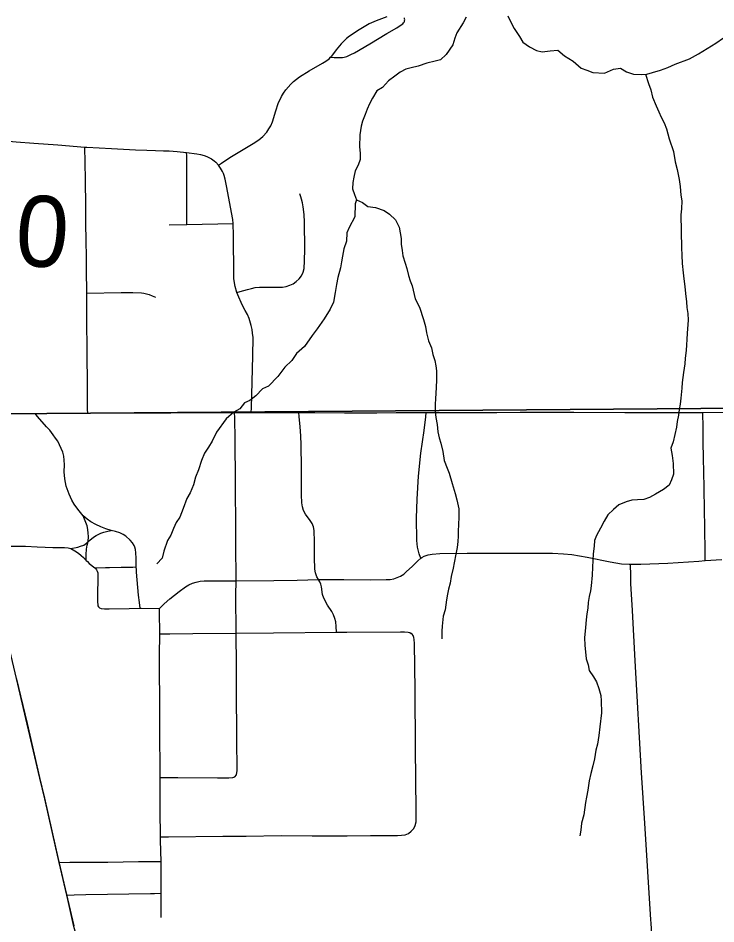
# Model space of a CAD drawing. Extents: x 0 to 34, y 0 to 22.
# Drawn here: x 20.417 to 20.975, y 12.198 to 12.923 of the extents above; entities that cross this region are included whole.
import ezdxf

# ---------------------------------------------------------------- set-up
doc = ezdxf.new("R2010")
doc.units = 0
for name, color, linetype in [('GM_X_City_Street', 7, 'Continuous'), ('GM_X_Corporation', 7, 'Continuous'), ('GM_X_County_Road', 7, 'Continuous'), ('GM_X_Minor_River', 7, 'Continuous'), ('GM_X_Section', 7, 'Continuous'), ('GM_X_State_Route', 7, 'Continuous'), ('GM_X_Township_Road', 7, 'Continuous'), ('GM_X_Township_Road_Text', 7, 'Continuous')]:
    doc.layers.add(name, color=color, linetype=linetype)

msp = doc.modelspace()

# ---------------------------------------------------------------- linework, layer by layer
at = {"layer": 'GM_X_City_Street'}
for points in [[(20.57722, 12.80519), (20.57964, 12.8068), (20.58622, 12.81118), (20.59689, 12.8177), (20.60476, 12.82263), (20.60941, 12.82555), (20.61263, 12.82812), (20.61579, 12.83164), (20.61755, 12.83424), (20.61909, 12.83677), (20.62027, 12.83992), (20.62291, 12.84873), (20.62496, 12.85459), (20.62749, 12.86024), (20.6291, 12.86289), (20.63091, 12.86542), (20.63496, 12.87013), (20.63718, 12.87223), (20.642, 12.87585), (20.6498, 12.88072), (20.66048, 12.88671), (20.66319, 12.88848), (20.66561, 12.89024), (20.6669, 12.89168), (20.66979, 12.89144), (20.67199, 12.89135), (20.67631, 12.8914), (20.67786, 12.89163), (20.67976, 12.89221), (20.68299, 12.89368), (20.686, 12.89514), (20.69832, 12.90233), (20.7119, 12.91069), (20.71982, 12.91516), (20.72261, 12.91692), (20.72481, 12.91846), (20.72533, 12.91905), (20.72574, 12.91959), (20.72602, 12.92025), (20.72616, 12.92088), (20.7262, 12.92161), (20.72616, 12.92237), (20.72599, 12.92317)], [(20.71193, 12.92391), (20.70349, 12.92074), (20.69787, 12.91821), (20.68987, 12.91355), (20.68208, 12.90849), (20.67965, 12.90659), (20.67522, 12.90231), (20.67127, 12.89757), (20.66767, 12.89256), (20.6669, 12.89168)], [(20.55173, 12.75767), (20.5518, 12.7697), (20.55176, 12.78036), (20.55173, 12.78904), (20.55169, 12.79911), (20.55163, 12.81255), (20.55162, 12.81521)], [(20.60323, 12.60701), (20.60347, 12.61094), (20.60466, 12.65257), (20.60476, 12.66728), (20.60447, 12.67073), (20.60398, 12.67369), (20.60329, 12.67675), (20.60161, 12.68237), (20.60023, 12.68553), (20.59856, 12.68879), (20.59599, 12.69343), (20.59254, 12.70132), (20.59193, 12.7033), (20.59047, 12.70803), (20.58988, 12.71089), (20.58939, 12.71434), (20.58929, 12.72668), (20.58918, 12.73921), (20.58909, 12.74888), (20.5888, 12.75841), (20.58855, 12.76161), (20.5834, 12.78871), (20.58238, 12.794), (20.58161, 12.79694), (20.58116, 12.79839), (20.58043, 12.79999), (20.57885, 12.80266), (20.57722, 12.80519)], [(20.59193, 12.7033), (20.59455, 12.70403), (20.60046, 12.70568), (20.60347, 12.70645), (20.60657, 12.70713), (20.60987, 12.70752), (20.61307, 12.70752), (20.62518, 12.70751), (20.62838, 12.70751), (20.63128, 12.70799), (20.63429, 12.70896), (20.63691, 12.71022), (20.63941, 12.71201), (20.64162, 12.71418), (20.64347, 12.71666), (20.64486, 12.71943), (20.64561, 12.72241), (20.64602, 12.72854), (20.64612, 12.73784), (20.64605, 12.75956), (20.64572, 12.76574), (20.64498, 12.77188), (20.64437, 12.77491), (20.64357, 12.7779), (20.64293, 12.77991), (20.64216, 12.78233)], [(20.53753, 12.75727), (20.55173, 12.75767), (20.5888, 12.75841)], [(20.47162, 12.70269), (20.49911, 12.7032), (20.50861, 12.70325), (20.51536, 12.70297), (20.51735, 12.70269), (20.51956, 12.70225), (20.52171, 12.70153), (20.52409, 12.70064), (20.5268, 12.69954)], [(20.47239, 12.60665), (20.47235, 12.60951), (20.47228, 12.61514), (20.47214, 12.62118), (20.47213, 12.63037), (20.4721, 12.6382), (20.47208, 12.64545), (20.47199, 12.65461), (20.47192, 12.66406), (20.47176, 12.6735), (20.47175, 12.68912), (20.47162, 12.70269)], [(20.46868, 12.52426), (20.46651, 12.52691), (20.46445, 12.52967), (20.46168, 12.53378), (20.45971, 12.53691), (20.45743, 12.54175), (20.45517, 12.54819), (20.45408, 12.554), (20.45362, 12.55971), (20.45372, 12.56525), (20.45354, 12.56906), (20.45319, 12.5722), (20.45234, 12.57528), (20.45122, 12.57833), (20.44991, 12.58122), (20.44836, 12.58402), (20.44668, 12.58663), (20.44474, 12.5893), (20.44193, 12.59293), (20.43948, 12.59556), (20.43222, 12.60401), (20.4302, 12.60636)], [(20.53052, 12.31476), (20.53494, 12.31476), (20.54465, 12.31476), (20.57638, 12.31442), (20.58528, 12.31448), (20.58861, 12.31475), (20.5902, 12.31541), (20.59151, 12.31692), (20.59213, 12.32045), (20.59178, 12.34539), (20.59142, 12.38594), (20.5916, 12.40463), (20.59132, 12.43043), (20.59098, 12.46078), (20.59114, 12.47231), (20.59121, 12.47635), (20.59098, 12.49817), (20.59088, 12.51834), (20.59075, 12.54477), (20.59068, 12.55173), (20.59034, 12.58508), (20.59009, 12.6027), (20.59004, 12.60702)], [(20.67156, 12.43116), (20.67124, 12.43563), (20.67098, 12.43934), (20.67031, 12.44221), (20.66926, 12.44496), (20.66785, 12.44763), (20.66442, 12.45279), (20.66145, 12.45845), (20.66049, 12.46148), (20.6596, 12.46753), (20.65905, 12.46969), (20.65835, 12.47148), (20.65751, 12.47274), (20.65717, 12.4733), (20.65587, 12.47553), (20.6552, 12.47707), (20.6547, 12.47859), (20.65418, 12.48172), (20.65409, 12.49107), (20.65399, 12.50344), (20.65362, 12.51268), (20.65318, 12.51562), (20.65214, 12.51823), (20.65057, 12.52068), (20.64674, 12.52564), (20.64528, 12.52857), (20.6443, 12.53165), (20.64374, 12.53482), (20.64347, 12.54109), (20.64349, 12.56274), (20.64332, 12.58125), (20.64307, 12.58839), (20.64252, 12.59564), (20.6417, 12.60386), (20.64139, 12.60701)], [(20.73922, 12.49035), (20.73894, 12.49109), (20.7378, 12.494), (20.73648, 12.49936), (20.73585, 12.50451), (20.73583, 12.50791), (20.73576, 12.51948), (20.73577, 12.52251), (20.73626, 12.53782), (20.73736, 12.55621), (20.73905, 12.57452), (20.74173, 12.5927), (20.74304, 12.60368), (20.74345, 12.60701)], [(20.96691, 12.48851), (20.9668, 12.4958), (20.96653, 12.51443), (20.96567, 12.56101), (20.96556, 12.5689), (20.96533, 12.58518), (20.96515, 12.59768), (20.96505, 12.60422), (20.96501, 12.60713)], [(20.47283, 12.50369), (20.47315, 12.50786), (20.47288, 12.51046), (20.47252, 12.51343), (20.47188, 12.51636), (20.46868, 12.52426)], [(20.51434, 12.4504), (20.51382, 12.45493), (20.51316, 12.4607), (20.51253, 12.46694), (20.51191, 12.47319), (20.5114, 12.47927), (20.51135, 12.48107), (20.5113, 12.48338), (20.51111, 12.49032), (20.51104, 12.49475), (20.51053, 12.49738), (20.51002, 12.49918), (20.5095, 12.50059), (20.50815, 12.50278), (20.50642, 12.5049), (20.5028, 12.5081), (20.50077, 12.50946), (20.49807, 12.51068), (20.49454, 12.5119), (20.49112, 12.51267), (20.48683, 12.51396), (20.48292, 12.5155), (20.47894, 12.51749), (20.47483, 12.51963), (20.47187, 12.52161), (20.46868, 12.52426)], [(20.47283, 12.50369), (20.47707, 12.50715), (20.47912, 12.50857), (20.48129, 12.50975), (20.48285, 12.51041), (20.48542, 12.51139), (20.48857, 12.51209), (20.49112, 12.51267)], [(20.39256, 12.49775), (20.39735, 12.4989), (20.40064, 12.4996), (20.40371, 12.49997), (20.41321, 12.5001), (20.42254, 12.49998), (20.43191, 12.49961), (20.43821, 12.49933), (20.44454, 12.49901), (20.44984, 12.49894), (20.45388, 12.49887), (20.45664, 12.49862), (20.45883, 12.49816)], [(20.45883, 12.49816), (20.46442, 12.49919), (20.46673, 12.49996), (20.46917, 12.50099), (20.47129, 12.5024), (20.47283, 12.50369)], [(20.45883, 12.49816), (20.46204, 12.49637), (20.46493, 12.49444), (20.46716, 12.49268), (20.46891, 12.49104), (20.47125, 12.48864), (20.47212, 12.48776), (20.47358, 12.48621), (20.4782, 12.4828), (20.479, 12.48187), (20.47948, 12.48119), (20.48005, 12.48002), (20.48037, 12.47869), (20.48048, 12.47702), (20.48031, 12.4586), (20.48032, 12.45531), (20.48042, 12.45346), (20.48063, 12.45226), (20.48101, 12.45139), (20.4819, 12.45065)], [(20.47125, 12.48864), (20.47122, 12.48956), (20.4711, 12.49341), (20.47142, 12.49759), (20.47206, 12.50092), (20.47283, 12.50369)], [(20.52996, 12.45024), (20.53373, 12.45389), (20.53827, 12.45792), (20.54558, 12.46372), (20.55066, 12.46738), (20.55338, 12.469), (20.55622, 12.47039), (20.55927, 12.47133), (20.56241, 12.47192), (20.56558, 12.47221), (20.58739, 12.47226), (20.59114, 12.47231), (20.62155, 12.47268), (20.64017, 12.4729), (20.65717, 12.4733), (20.66192, 12.47341), (20.67748, 12.47338), (20.69911, 12.47304), (20.71142, 12.47325), (20.71446, 12.47348), (20.71742, 12.47399), (20.72026, 12.47486), (20.72292, 12.47612), (20.72542, 12.47775), (20.72777, 12.47965), (20.7322, 12.4839), (20.73661, 12.48837), (20.73922, 12.49035), (20.74002, 12.49095), (20.74189, 12.49204), (20.74495, 12.49313), (20.74811, 12.49375), (20.75442, 12.49421), (20.77619, 12.49439), (20.81657, 12.4944), (20.84455, 12.49457), (20.85342, 12.49404), (20.86013, 12.49343), (20.87244, 12.4913), (20.89065, 12.48741), (20.89979, 12.48602), (20.90592, 12.48566), (20.907, 12.48566), (20.91517, 12.48562), (20.93684, 12.48657), (20.96164, 12.48813), (20.96691, 12.48851), (20.98022, 12.48946)], [(20.4782, 12.4828), (20.48664, 12.48293), (20.48976, 12.48298), (20.49927, 12.48313), (20.50861, 12.48334), (20.5113, 12.48338)], [(20.92437, 12.18511), (20.92353, 12.1981), (20.92342, 12.20081), (20.91846, 12.27817), (20.91583, 12.31842), (20.91063, 12.40823), (20.90864, 12.44849), (20.9074, 12.47018), (20.90723, 12.4764), (20.907, 12.48566)], [(20.4819, 12.45065), (20.48315, 12.45009), (20.48582, 12.44985), (20.48946, 12.4498), (20.50552, 12.45023), (20.51434, 12.4504), (20.51522, 12.45042), (20.52996, 12.45024)], [(20.53129, 12.2026), (20.53129, 12.22215), (20.53129, 12.23655), (20.53108, 12.24745), (20.53075, 12.26435), (20.5307, 12.26726), (20.53051, 12.28825), (20.53042, 12.29826), (20.53052, 12.31476), (20.53054, 12.31989), (20.53024, 12.35077), (20.53006, 12.38034), (20.52996, 12.39709), (20.52985, 12.41252), (20.53002, 12.42978), (20.53006, 12.43407), (20.53, 12.44316), (20.52996, 12.45024)], [(20.53002, 12.42978), (20.53802, 12.42987), (20.55653, 12.43009), (20.59132, 12.43043), (20.62126, 12.43072), (20.67156, 12.43116), (20.67985, 12.43124), (20.72297, 12.43158), (20.72614, 12.43149), (20.72893, 12.43119), (20.73027, 12.43082), (20.73143, 12.43019)], [(20.5307, 12.26726), (20.53698, 12.26732), (20.58056, 12.26774), (20.59922, 12.26792), (20.62723, 12.26824), (20.65213, 12.26814), (20.68014, 12.26815), (20.69878, 12.26832), (20.71125, 12.26849), (20.72056, 12.26841), (20.7236, 12.26855), (20.72653, 12.26896), (20.72915, 12.27004), (20.7315, 12.27176), (20.7334, 12.27394), (20.73466, 12.27646), (20.73528, 12.27928), (20.73541, 12.28849), (20.73497, 12.33829), (20.73453, 12.38496), (20.73406, 12.42223), (20.73381, 12.42528), (20.73346, 12.42687), (20.7329, 12.42845), (20.73223, 12.42953), (20.73143, 12.43019)], [(20.44955, 12.24684), (20.45812, 12.24688), (20.48857, 12.24702), (20.51293, 12.24752), (20.52511, 12.24748), (20.53108, 12.24745)], [(20.4556, 12.22045), (20.46168, 12.22075), (20.47082, 12.22119), (20.52271, 12.22189), (20.52576, 12.22198), (20.53129, 12.22215)]]:
    msp.add_lwpolyline(points, dxfattribs=at)
at = {"layer": 'GM_X_Corporation'}
msp.add_lwpolyline([(20.41515, 12.39457), (20.42379, 12.35798), (20.43386, 12.31492), (20.43774, 12.2982), (20.44666, 12.25902), (20.44934, 12.24739), (20.45539, 12.221), (20.45616, 12.21768), (20.4612, 12.19593)], dxfattribs=at)
at = {"layer": 'GM_X_County_Road'}
msp.add_line((20.59004, 12.60702), (20.60323, 12.60701), dxfattribs=at)
for points in [[(20.36972, 12.60531), (20.38241, 12.60559), (20.39518, 12.60575), (20.40443, 12.60592), (20.42933, 12.60635), (20.4302, 12.60636)], [(20.4302, 12.60636), (20.46489, 12.60665), (20.47239, 12.60665)], [(20.47239, 12.60665), (20.49262, 12.60694), (20.52044, 12.60693), (20.5389, 12.60693), (20.576, 12.60702), (20.59004, 12.60702)], [(20.60323, 12.60701), (20.63115, 12.60701), (20.64139, 12.60701)], [(20.64139, 12.60701), (20.65414, 12.607), (20.67792, 12.60693), (20.69065, 12.6069)], [(20.69065, 12.6069), (20.70387, 12.6069), (20.71927, 12.60709), (20.74345, 12.60701)], [(20.74345, 12.60701), (20.75035, 12.60698), (20.77206, 12.60718), (20.8, 12.60722), (20.81862, 12.60726), (20.86175, 12.60726), (20.9025, 12.60715), (20.94246, 12.60714), (20.95827, 12.60704), (20.96501, 12.60713)], [(20.96501, 12.60713), (20.98588, 12.60743), (21.01077, 12.60773), (21.05082, 12.60807), (21.07564, 12.6082), (21.09427, 12.60828), (21.11288, 12.60841), (21.12991, 12.60876)]]:
    msp.add_lwpolyline(points, dxfattribs=at)
at = {"layer": 'GM_X_Minor_River'}
for points in [[(20.77538, 12.92366), (20.77316, 12.91908), (20.76794, 12.91103), (20.76647, 12.90683), (20.76464, 12.90149), (20.75942, 12.89382), (20.75491, 12.88958), (20.75074, 12.88839), (20.74391, 12.88678), (20.7371, 12.8844), (20.73141, 12.88319), (20.72724, 12.882), (20.72271, 12.87965), (20.71818, 12.87656), (20.71329, 12.87269), (20.70842, 12.86731), (20.70388, 12.86459), (20.70054, 12.85885), (20.69793, 12.85426), (20.69609, 12.85005), (20.69462, 12.84585), (20.69241, 12.84051), (20.69132, 12.83631), (20.69027, 12.82946), (20.69001, 12.81996), (20.69046, 12.81465), (20.69053, 12.80971), (20.68906, 12.80513), (20.68646, 12.80054), (20.68538, 12.79559), (20.68468, 12.7914), (20.68437, 12.78608), (20.68595, 12.78154), (20.68752, 12.77738), (20.69249, 12.77517), (20.69672, 12.77219), (20.70282, 12.77113), (20.70969, 12.76894), (20.71392, 12.76596), (20.71892, 12.76147), (20.72166, 12.75543), (20.7233, 12.74633), (20.72335, 12.74178), (20.72418, 12.73685), (20.72461, 12.73267), (20.7266, 12.72662), (20.72779, 12.72246), (20.72938, 12.71678), (20.73058, 12.71262), (20.73216, 12.70847), (20.73457, 12.69824), (20.73808, 12.69145), (20.74125, 12.68162), (20.74285, 12.67594), (20.74367, 12.67101), (20.74528, 12.66458), (20.74763, 12.65891), (20.74884, 12.65361), (20.75043, 12.64869), (20.75124, 12.64452), (20.75168, 12.64035), (20.75177, 12.63313), (20.75147, 12.62705), (20.75083, 12.61793), (20.7505, 12.61374), (20.75057, 12.60805), (20.75102, 12.60312), (20.75223, 12.59743), (20.75269, 12.59174), (20.75389, 12.58682), (20.75509, 12.58266), (20.7567, 12.57584), (20.75793, 12.56864), (20.76029, 12.56259), (20.76187, 12.55844), (20.76426, 12.55011), (20.76664, 12.54217), (20.76785, 12.53724), (20.76946, 12.53005), (20.76955, 12.52321), (20.76925, 12.51751), (20.76893, 12.51219), (20.76899, 12.50801), (20.76866, 12.50383), (20.76835, 12.49888), (20.76728, 12.49355), (20.76584, 12.48669), (20.76513, 12.48251), (20.76332, 12.47565), (20.76263, 12.47032), (20.76117, 12.46574), (20.76046, 12.46155), (20.75976, 12.45698), (20.75873, 12.44899), (20.75689, 12.44403), (20.75623, 12.43605)], [(20.80884, 12.92487), (20.8108, 12.92033), (20.81391, 12.91468), (20.81818, 12.90828), (20.8209, 12.90376), (20.82627, 12.90003), (20.83164, 12.89706), (20.83621, 12.89598), (20.84267, 12.89683), (20.84875, 12.89729), (20.85413, 12.8928), (20.86104, 12.88834), (20.86757, 12.88273), (20.87216, 12.88127), (20.87674, 12.87943), (20.88626, 12.8788), (20.89345, 12.88193), (20.89914, 12.88277), (20.90374, 12.87979), (20.90947, 12.87797), (20.91556, 12.87767), (20.92012, 12.87811), (20.92467, 12.87931), (20.93111, 12.88129), (20.93679, 12.88327), (20.94284, 12.88601), (20.95419, 12.89034), (20.96137, 12.89423), (20.97533, 12.90278), (20.98136, 12.90703)], [(20.91892, 12.87799), (20.92136, 12.87053), (20.92333, 12.86562), (20.92454, 12.85955), (20.92768, 12.85276), (20.92964, 12.84785), (20.9316, 12.84369), (20.93394, 12.83917), (20.9359, 12.83425), (20.93791, 12.8263), (20.94146, 12.8161), (20.94271, 12.80776), (20.94431, 12.8017), (20.94594, 12.79374), (20.94677, 12.78806), (20.94724, 12.78123), (20.94806, 12.77668), (20.94777, 12.77022), (20.94745, 12.76527), (20.94779, 12.73907), (20.94825, 12.733), (20.94833, 12.72654), (20.94919, 12.71895), (20.94963, 12.71402), (20.95047, 12.70795), (20.95093, 12.70226), (20.95177, 12.69582), (20.95221, 12.69126), (20.95304, 12.68634), (20.95311, 12.68102), (20.95248, 12.67076), (20.95217, 12.66543), (20.95184, 12.66125), (20.95152, 12.65669), (20.95084, 12.6506), (20.95052, 12.64604), (20.94946, 12.63919), (20.94843, 12.63119), (20.94811, 12.62663), (20.94745, 12.61865), (20.94675, 12.6137), (20.94605, 12.60951), (20.94535, 12.60494), (20.94427, 12.59999), (20.94395, 12.59543), (20.94106, 12.58362), (20.93922, 12.57865), (20.94044, 12.57259), (20.94128, 12.56615), (20.94139, 12.55779), (20.93993, 12.55321), (20.93809, 12.54901), (20.93357, 12.54553), (20.92715, 12.54164), (20.92224, 12.53892), (20.9177, 12.53734), (20.91275, 12.53727), (20.9082, 12.53683), (20.90365, 12.53563), (20.8976, 12.53327), (20.89346, 12.52942), (20.88895, 12.52518), (20.88597, 12.5202), (20.883, 12.51447), (20.87966, 12.50872), (20.87819, 12.50453), (20.87787, 12.49996), (20.87719, 12.49388), (20.87688, 12.48855), (20.87656, 12.48323), (20.87627, 12.47677), (20.87562, 12.4684), (20.87491, 12.46422), (20.87383, 12.45964), (20.87313, 12.45508), (20.87281, 12.45051), (20.8721, 12.44595), (20.87141, 12.441), (20.87111, 12.43492), (20.87007, 12.42655), (20.87053, 12.42085), (20.87143, 12.40985), (20.87302, 12.40493), (20.87384, 12.40038), (20.87732, 12.39549), (20.87966, 12.39135), (20.88163, 12.38605), (20.88322, 12.38038), (20.88366, 12.3762), (20.88378, 12.36671), (20.88241, 12.3553), (20.88174, 12.34845), (20.88068, 12.3416), (20.87923, 12.33664), (20.87818, 12.32979), (20.87673, 12.32407), (20.87529, 12.31798), (20.87384, 12.31226), (20.8728, 12.30465), (20.87173, 12.29893), (20.87103, 12.29475)], [(20.68752, 12.77738), (20.68642, 12.77433), (20.68618, 12.76369), (20.68172, 12.75528), (20.67988, 12.75107), (20.67959, 12.74423), (20.67738, 12.73812), (20.67631, 12.73241), (20.67561, 12.72784), (20.67492, 12.7229), (20.67274, 12.71527), (20.67167, 12.70956), (20.67061, 12.70309), (20.66919, 12.69547), (20.6666, 12.68974), (20.66176, 12.68208), (20.65616, 12.67402), (20.65204, 12.66865), (20.64607, 12.65983), (20.63968, 12.65443), (20.63595, 12.64868), (20.63031, 12.64329), (20.6247, 12.636), (20.61719, 12.6283), (20.61228, 12.62596), (20.60703, 12.62057), (20.60213, 12.61671), (20.59797, 12.61475), (20.59423, 12.61014), (20.58932, 12.60742), (20.58331, 12.60202), (20.57546, 12.59128), (20.57213, 12.58402), (20.56915, 12.57942), (20.56579, 12.57444), (20.56358, 12.56871), (20.56102, 12.56108), (20.55881, 12.55535), (20.55699, 12.54925), (20.55441, 12.54276), (20.55181, 12.53816), (20.54887, 12.53015), (20.54629, 12.52328), (20.54331, 12.51906), (20.54109, 12.51409), (20.53888, 12.50874), (20.53627, 12.50453), (20.53334, 12.49613), (20.53189, 12.49042), (20.52776, 12.4858)], [(20.75623, 12.43605), (20.7559, 12.43186), (20.75599, 12.42579)], [(20.87103, 12.29475), (20.86963, 12.28485), (20.86781, 12.27837), (20.86713, 12.27266), (20.86643, 12.26809)]]:
    msp.add_lwpolyline(points, dxfattribs=at)
at = {"layer": 'GM_X_Section'}
for points in [[(21.2938, 13.61037), (21.31252, 12.61292), (20.26496, 12.60488), (20.2632, 13.61532)], [(20.26496, 12.60488), (21.31252, 12.61292), (21.31182, 11.93487), (21.29872, 11.60315), (20.27005, 11.60623)]]:
    msp.add_lwpolyline(points, close=True, dxfattribs=at)
at = {"layer": 'GM_X_State_Route'}
msp.add_lwpolyline([(20.47047, 12.16569), (20.46886, 12.1705), (20.46676, 12.17662), (20.46518, 12.18169), (20.46141, 12.19538), (20.45637, 12.21714), (20.4556, 12.22045), (20.44955, 12.24684), (20.44687, 12.25848), (20.43795, 12.29765), (20.43407, 12.31437), (20.424, 12.35744), (20.41536, 12.39402), (20.40571, 12.43493), (20.40453, 12.44031)], dxfattribs=at)
at = {"layer": 'GM_X_Township_Road'}
msp.add_line((20.47162, 12.70269), (20.47159, 12.70766), dxfattribs=at)
for points in [[(20.34422, 12.8472), (20.35429, 12.84297), (20.37343, 12.83436), (20.38191, 12.83081), (20.39099, 12.82795), (20.3979, 12.82627), (20.40641, 12.82478), (20.41517, 12.82386), (20.42937, 12.8228), (20.44851, 12.82133), (20.47016, 12.81965)], [(20.47016, 12.81965), (20.4716, 12.81954), (20.49153, 12.81855), (20.51064, 12.8175), (20.51971, 12.81718), (20.52663, 12.81694), (20.5331, 12.81671)], [(20.47065, 12.79257), (20.47064, 12.79354), (20.47041, 12.80721), (20.47016, 12.81965)], [(20.5331, 12.81671), (20.53758, 12.81655), (20.54395, 12.81607), (20.55162, 12.81521)], [(20.55162, 12.81521), (20.55983, 12.81415), (20.56261, 12.81359), (20.56552, 12.81284), (20.56776, 12.812), (20.56997, 12.81096), (20.57148, 12.81013), (20.57373, 12.80859), (20.57486, 12.80757), (20.57722, 12.80519)], [(20.47082, 12.76966), (20.47078, 12.77307), (20.47065, 12.79257)], [(20.47101, 12.75467), (20.47096, 12.76006), (20.47087, 12.76625), (20.47082, 12.76966)], [(20.47134, 12.73365), (20.47121, 12.74283), (20.47112, 12.74853), (20.47101, 12.75467)], [(20.47159, 12.70766), (20.47157, 12.70975), (20.47149, 12.71446), (20.47145, 12.72035), (20.47141, 12.72474), (20.47136, 12.73001), (20.47134, 12.73365)]]:
    msp.add_lwpolyline(points, dxfattribs=at)

# ---------------------------------------------------------------- texts
at = {"layer": 'GM_X_Township_Road_Text'}
msp.add_text('0', height=0.05682, rotation=355.94735, dxfattribs=at).set_placement((20.41307, 12.72532))

doc.saveas('drawing.dxf')
